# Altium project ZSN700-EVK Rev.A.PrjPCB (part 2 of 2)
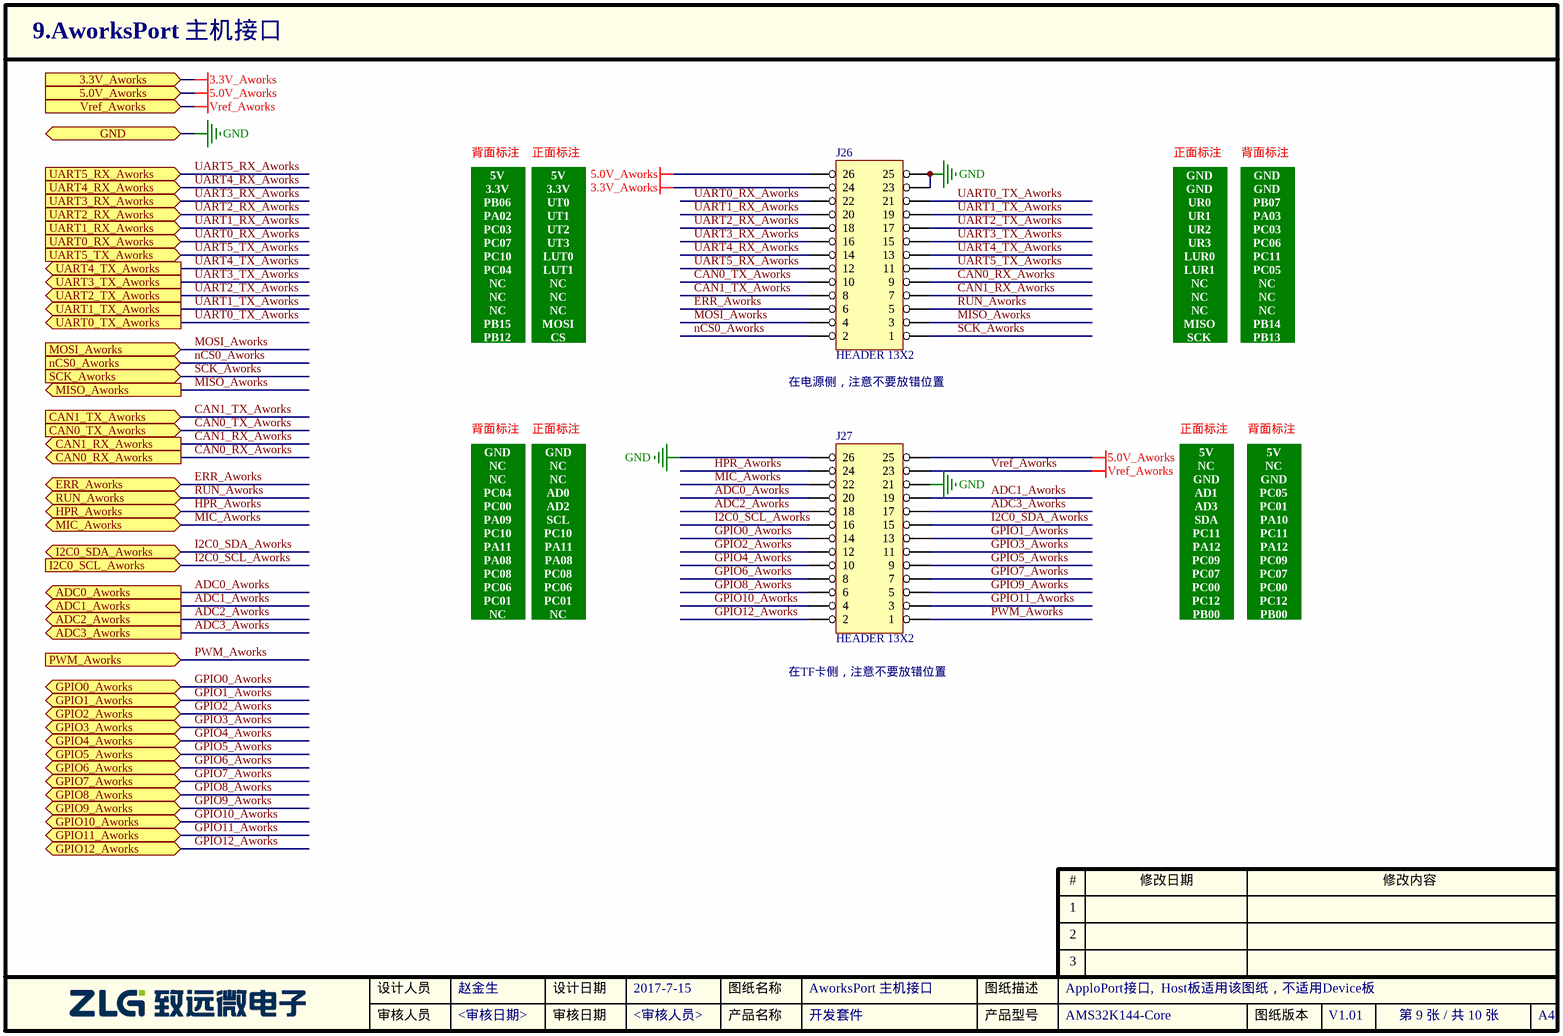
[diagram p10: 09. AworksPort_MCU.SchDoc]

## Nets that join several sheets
3.3V: 06. Peripheral (R57.1), 08. MiniPort (J25.1), 07. MicroPort (J23.26 J24.3), 03. ZSN700 (14 pins), 02. POWER (6 pins), 04. SAM (R53.1), 05. Analog Multiplexer (R55.1), 09. AworksPort_MCU (J26.24 J27.23)
5.0V_Aworks: 06. Peripheral (R56.1), 08. MiniPort (J25.2), 07. MicroPort (J24.1), 03. ZSN700 (J5.1), 02. POWER (7 pins), 05. Analog Multiplexer (R54.1), 09. AworksPort_MCU (J26.26 J27.25)
8V: 02. POWER (R50.2 T3.1), 05. Analog Multiplexer (R37.1)
-5V: 02. POWER (R51.2 T4.1), 05. Analog Multiplexer (R39.1)
EARTH1: 01. Main (C1.1 HOLE4.1 R1.2), 02. POWER (6 pins)
GND: 01. Main (C1.2 R1.1), 06. Peripheral (9 pins), 08. MiniPort (J25.3 J25.4), 07. MicroPort (J23.1), 03. ZSN700 (27 pins), 02. POWER (23 pins), 04. SAM (9 pins), 05. Analog Multiplexer (12 pins), 10. LCD Port (J28.25 J28.26), 09. AworksPort_MCU (J26.23 J26.25 J27.21 J27.26)
ADC0_Aworks: 07. MicroPort (J23.17), 03. ZSN700 (U3.50), 09. AworksPort_MCU (J26.12 J27.20)
ADC1_Aworks: 07. MicroPort (J23.16), 03. ZSN700 (U3.51), 09. AworksPort_MCU (J26.11 J27.19)
ADC2_Aworks: 08. MiniPort (J25.5), 03. ZSN700 (U3.38), 10. LCD Port (J28.10), 09. AworksPort_MCU (J27.5 J27.18)
ADC3_Aworks: 08. MiniPort (J25.6), 03. ZSN700 (U3.39), 10. LCD Port (J28.11), 09. AworksPort_MCU (J27.4 J27.17)
AM4051_ENn: 03. ZSN700 (U3.63), 05. Analog Multiplexer (Q5.2)
AM4051_S1: 03. ZSN700 (U3.23), 05. Analog Multiplexer (Q2.2)
AM4051_S2: 03. ZSN700 (U3.20), 05. Analog Multiplexer (Q3.2)
AM4051_S3: 03. ZSN700 (U3.19), 05. Analog Multiplexer (Q4.2)
AM4051_TX: 03. ZSN700 (R12.2 R13.2), 05. Analog Multiplexer (U6.3)
COM0: 03. ZSN700 (U3.17), 10. LCD Port (J28.1), 09. AworksPort_MCU (J26.14 J27.14)
COM1: 03. ZSN700 (U3.15), 10. LCD Port (J28.2), 09. AworksPort_MCU (J26.13 J27.13)
COM2: 07. MicroPort (J23.11), 03. ZSN700 (U3.3), 10. LCD Port (J28.3), 09. AworksPort_MCU (J27.12)
COM3: 07. MicroPort (J23.10), 03. ZSN700 (U3.4), 10. LCD Port (J28.4), 09. AworksPort_MCU (J27.11)
GPIO4_Aworks: 06. Peripheral (J20.1 R48.1), 07. MicroPort (J23.14), 03. ZSN700 (U3.68), 10. LCD Port (J28.5), 09. AworksPort_MCU (J27.10)
GPIO5_Aworks: 08. MiniPort (J25.11), 03. ZSN700 (U3.67), 10. LCD Port (J28.6), 09. AworksPort_MCU (J27.9)
GPIO6_Aworks: 08. MiniPort (J25.8), 03. ZSN700 (U3.66), 10. LCD Port (J28.7), 09. AworksPort_MCU (J27.8)
GPIO7_Aworks: 03. ZSN700 (U3.65), 10. LCD Port (J28.8), 09. AworksPort_MCU (J26.16 J27.7)
GPIO8_Aworks: 03. ZSN700 (U3.64), 10. LCD Port (J28.9), 09. AworksPort_MCU (J26.15 J27.6)
GPIO11_Aworks: 07. MicroPort (J23.2), 03. ZSN700 (U3.16), 10. LCD Port (J28.12), 09. AworksPort_MCU (J27.3)
GPIO_LED0: 06. Peripheral (J17.1), 07. MicroPort (J23.5), 03. ZSN700 (U3.6)
GPIO_LED1: 06. Peripheral (J19.1), 07. MicroPort (J23.23), 03. ZSN700 (U3.7)
I2C0_SCL_Aworks: 06. Peripheral (J21.1), 08. MiniPort (J25.17), 07. MicroPort (J23.12), 03. ZSN700 (U3.1), 09. AworksPort_MCU (J27.16)
I2C0_SDA_Aworks: 06. Peripheral (J22.1), 08. MiniPort (J25.19), 07. MicroPort (J23.13), 03. ZSN700 (U3.2), 09. AworksPort_MCU (J27.15)
MicroPort_CS: 08. MiniPort (J25.7), 07. MicroPort (J23.22), 03. ZSN700 (U3.9), 09. AworksPort_MCU (J26.2)
MicroPort_CTS: 07. MicroPort (J23.7), 03. ZSN700 (U3.44)
MicroPort_DAC: 07. MicroPort (J23.15), 03. ZSN700 (U3.14)
MicroPort_MISO: 08. MiniPort (J25.9), 07. MicroPort (J23.20), 03. ZSN700 (U3.11), 09. AworksPort_MCU (J26.3)
MicroPort_MOSI: 08. MiniPort (J25.15), 07. MicroPort (J23.21), 03. ZSN700 (U3.12), 09. AworksPort_MCU (J26.4)
MicroPort_PWM0: 06. Peripheral (J18.1), 07. MicroPort (J23.3), 03. ZSN700 (U3.49)
MicroPort_PWM1: 07. MicroPort (J23.4), 03. ZSN700 (U3.48)
MicroPort_PWM2: 07. MicroPort (J23.25), 03. ZSN700 (U3.52), 09. AworksPort_MCU (J27.1)
MicroPort_PWM3: 07. MicroPort (J23.24), 03. ZSN700 (U3.53)
MicroPort_RTS: 07. MicroPort (J23.6), 03. ZSN700 (U3.45)
MicroPort_RXD: 08. MiniPort (J25.10), 07. MicroPort (J23.9), 03. ZSN700 (U3.47), 09. AworksPort_MCU (J26.19)
MicroPort_SCK: 08. MiniPort (J25.13), 07. MicroPort (J23.19), 03. ZSN700 (U3.10), 09. AworksPort_MCU (J26.1)
MicroPort_TXD: 08. MiniPort (J25.12), 07. MicroPort (J23.8), 03. ZSN700 (U3.46), 09. AworksPort_MCU (J26.20)
MiniPort_I/O4: 08. MiniPort (J25.14), 03. ZSN700 (U3.42), 09. AworksPort_MCU (J26.17)
MiniPort_I/O5: 08. MiniPort (J25.16), 03. ZSN700 (U3.43), 09. AworksPort_MCU (J26.18)
MiniPort_I/O6: 08. MiniPort (J25.18), 03. ZSN700 (U3.24), 09. AworksPort_MCU (J26.22)
MiniPort_I/O7: 08. MiniPort (J25.20), 03. ZSN700 (U3.25), 09. AworksPort_MCU (J26.21)
PB08: 03. ZSN700 (U3.27), 04. SAM (5 pins)
PB09: 03. ZSN700 (U3.28), 04. SAM (5 pins)
PC13: 03. ZSN700 (U3.32), 04. SAM (LED5.2 T10.1 U4.3 U5.6)
PD02: 03. ZSN700 (U3.18), 04. SAM (LED2.2 R19.1)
